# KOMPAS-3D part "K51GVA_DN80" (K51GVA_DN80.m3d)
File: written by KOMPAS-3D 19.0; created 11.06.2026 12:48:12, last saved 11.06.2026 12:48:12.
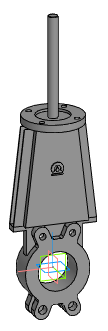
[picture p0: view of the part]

Document properties: Автор: Энергия; Полное имя файла: Z:\3.Личные\kachalov\001_3d для проектировщиков\2.6 Тип_K51GVA. Задвижка\_stp\_stp_K51GVA_DN50-DN1000_с фланцем\K51GVA_DN80.m3d

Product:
- Part/product: K51GVA_DN80

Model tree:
1. Операция без истории:1  (labels: K51GVA_DN80)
